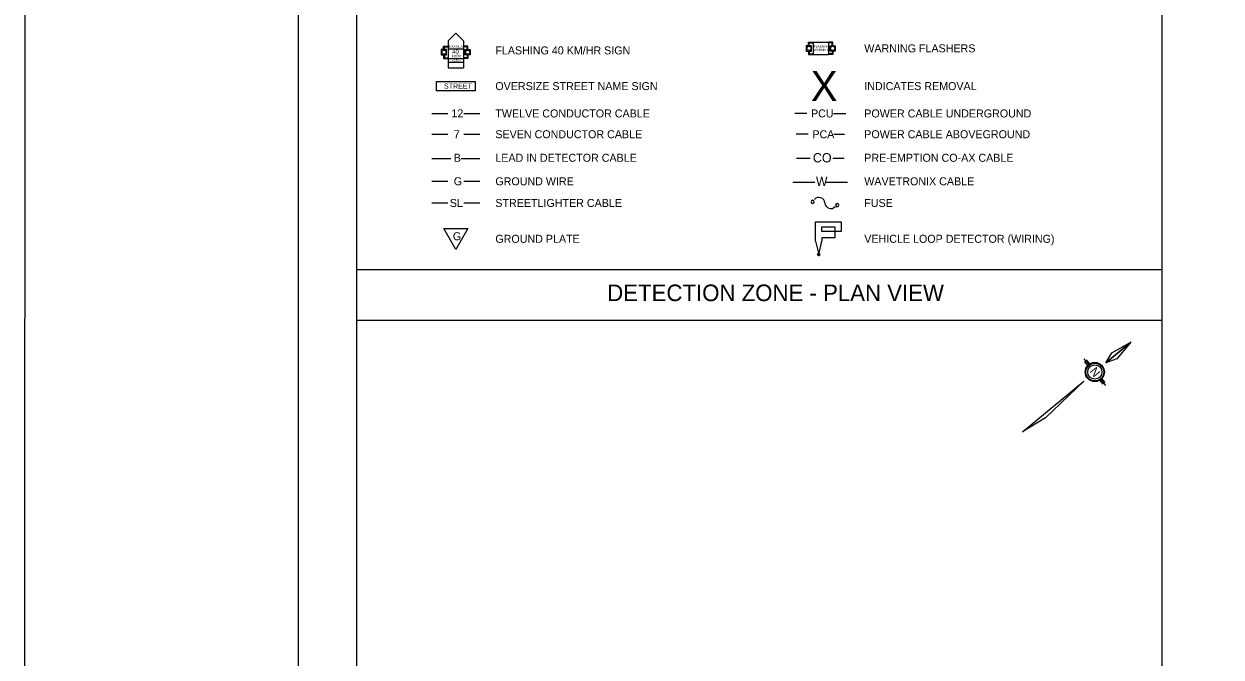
# Model space of a CAD drawing. Extents: x 595568 to 603392, y 4837996 to 4846579.
# Drawn here: x 603041.8 to 603106.7, y 4846467.9 to 4846502.2 of the extents above; entities that cross this region are included whole.
import ezdxf

# ---------------------------------------------------------------- set-up
doc = ezdxf.new("R2010")
doc.units = 0
for name, color, linetype in [('-PRINT FULLSIZE', 7, 'Continuous'), ('-PRINT HALFSIZE', 7, 'Continuous'), ('ENG_BORDER', 7, 'Continuous'), ('ENG_KEY', 7, 'Continuous'), ('ENG_TITLEBLOCK', 7, 'Continuous'), ('ENG_TX_TITLEBLOCK', 7, 'Continuous'), ('TCS_FUSE', 7, 'Continuous'), ('TCS_LEGEND', 7, 'Continuous'), ('TCS_LOOP', 7, 'Continuous'), ('TCS_PLATE', 7, 'Continuous'), ('TCS_REMOVAL', 7, 'Continuous'), ('TCS_SIGN', 7, 'Continuous'), ('TCS_WR_12', 7, 'Continuous'), ('TCS_WR_7', 7, 'Continuous'), ('TCS_WR_B', 7, 'Continuous'), ('TCS_WR_CO', 7, 'Continuous'), ('TCS_WR_G', 7, 'Continuous'), ('TCS_WR_PCA', 7, 'Continuous'), ('TCS_WR_PCU', 7, 'Continuous'), ('TCS_WR_SL', 7, 'Continuous'), ('TCS_WR_W', 7, 'Continuous')]:
    doc.layers.add(name, color=color, linetype=linetype)

msp = doc.modelspace()

# ---------------------------------------------------------------- linework, layer by layer
at = {"layer": '-PRINT FULLSIZE'}
msp.add_lwpolyline([(603041.762, 4846390.886), (603265.214, 4846390.798), (603265.274, 4846543.386), (603041.822, 4846543.475)], close=True, dxfattribs=at)
at = {"layer": '-PRINT HALFSIZE'}
msp.add_lwpolyline([(603056.659, 4846536.385), (603261.877, 4846536.304), (603261.821, 4846396.201), (603056.604, 4846396.282)], close=True, dxfattribs=at)
at = {"layer": 'ENG_BORDER'}
msp.add_line((603103.463, 4846399.391), (603103.462, 4846533.885), dxfattribs=at)
msp.add_lwpolyline([(603059.791, 4846533.885), (603059.791, 4846399.391)], dxfattribs=at)
at = {"layer": 'ENG_KEY'}
for p, q in [((603099.487, 4846483.734), (603099.222, 4846484.055)), ((603099.437, 4846483.686), (603099.259, 4846483.901)), ((603099.544, 4846483.775), (603099.366, 4846483.989)), ((603100.27, 4846482.677), (603100.092, 4846482.892)), ((603100.414, 4846482.612), (603100.148, 4846482.933)), ((603100.377, 4846482.766), (603100.199, 4846482.981))]:
    msp.add_line(p, q, dxfattribs=at)
for points in [[(603101.776, 4846484.951), (603101.006, 4846484.046), (603100.423, 4846483.833)], [(603101.776, 4846484.951), (603100.423, 4846483.833), (603100.742, 4846484.366)], [(603099.213, 4846482.833), (603097.138, 4846480.85), (603095.901, 4846480.099)]]:
    msp.add_lwpolyline(points, close=True, dxfattribs=at)
for radius in [0.52, 0.482, 0.388]:
    msp.add_circle((603099.818, 4846483.333), radius, dxfattribs=at)
at = {"layer": 'ENG_TITLEBLOCK'}
msp.add_line((603059.791, 4846486.146), (603103.462, 4846486.146), dxfattribs=at)
msp.add_lwpolyline([(603059.791, 4846488.897), (603103.462, 4846488.896)], dxfattribs=at)
at = {"layer": 'TCS_FUSE'}
for centre, radius, start, end in [((603084.521, 4846492.56), 0.0867, 0, 180), ((603084.521, 4846492.56), 0.0867, 180, 0), ((603084.867, 4846492.486), 0.319, 2.71733, 139.36608), ((603085.505, 4846492.516), 0.319, 182.71733, 319.36608), ((603085.853, 4846492.382), 0.0867, 0, 180), ((603085.853, 4846492.382), 0.0867, 180, 0)]:
    msp.add_arc(centre, radius, start, end, dxfattribs=at)
at = {"layer": 'TCS_LEGEND'}
msp.add_lwpolyline([(603099.121, 4846488.896), (603099.121, 4846488.881), (603064.132, 4846488.881), (603064.132, 4846488.897)], dxfattribs=at)
at = {"layer": 'TCS_LOOP'}
for p, q in [((603084.674, 4846491.47), (603086.062, 4846491.47)), ((603084.674, 4846490.429), (603084.674, 4846491.47)), ((603085.021, 4846491.21), (603085.715, 4846491.21)), ((603085.021, 4846490.949), (603085.021, 4846491.21)), ((603086.062, 4846490.949), (603085.021, 4846490.949)), ((603085.715, 4846491.21), (603085.715, 4846490.602)), ((603086.062, 4846491.47), (603086.062, 4846490.949)), ((603084.674, 4846490.429), (603084.847, 4846489.704)), ((603084.847, 4846489.704), (603085.021, 4846490.422)), ((603085.021, 4846490.602), (603085.021, 4846490.422)), ((603085.715, 4846490.602), (603085.021, 4846490.602)), ((603084.788, 4846489.697), (603084.854, 4846489.764)), ((603084.788, 4846489.702), (603084.849, 4846489.764)), ((603084.788, 4846489.707), (603084.844, 4846489.764)), ((603084.788, 4846489.713), (603084.839, 4846489.763)), ((603084.789, 4846489.693), (603084.859, 4846489.763)), ((603084.789, 4846489.719), (603084.832, 4846489.762)), ((603084.79, 4846489.689), (603084.863, 4846489.762)), ((603084.791, 4846489.685), (603084.867, 4846489.761)), ((603084.792, 4846489.681), (603084.87, 4846489.759)), ((603084.792, 4846489.727), (603084.824, 4846489.759)), ((603084.794, 4846489.678), (603084.874, 4846489.758)), ((603084.796, 4846489.674), (603084.877, 4846489.756)), ((603084.798, 4846489.671), (603084.88, 4846489.754)), ((603084.798, 4846489.738), (603084.813, 4846489.753)), ((603084.8, 4846489.668), (603084.883, 4846489.752)), ((603084.802, 4846489.665), (603084.886, 4846489.75)), ((603084.804, 4846489.663), (603084.889, 4846489.747)), ((603084.807, 4846489.66), (603084.891, 4846489.745)), ((603084.81, 4846489.658), (603084.894, 4846489.742)), ((603084.813, 4846489.656), (603084.896, 4846489.739)), ((603084.816, 4846489.654), (603084.898, 4846489.736)), ((603084.819, 4846489.652), (603084.9, 4846489.733)), ((603084.822, 4846489.65), (603084.901, 4846489.729)), ((603084.826, 4846489.648), (603084.903, 4846489.726)), ((603084.83, 4846489.647), (603084.904, 4846489.722)), ((603084.834, 4846489.646), (603084.905, 4846489.718)), ((603084.838, 4846489.645), (603084.906, 4846489.713)), ((603084.843, 4846489.645), (603084.907, 4846489.709)), ((603084.848, 4846489.645), (603084.907, 4846489.704)), ((603084.853, 4846489.645), (603084.907, 4846489.699)), ((603084.859, 4846489.646), (603084.906, 4846489.693)), ((603084.866, 4846489.648), (603084.904, 4846489.686)), ((603084.875, 4846489.651), (603084.9, 4846489.677))]:
    msp.add_line(p, q, dxfattribs=at)
msp.add_circle((603084.847, 4846489.704), 0.0597, dxfattribs=at)
at = {"layer": 'TCS_PLATE'}
for p, q in [((603065.176, 4846489.986), (603064.525, 4846491.113)), ((603064.525, 4846491.113), (603065.827, 4846491.113)), ((603065.827, 4846491.113), (603065.176, 4846489.986))]:
    msp.add_line(p, q, dxfattribs=at)
at = {"layer": 'TCS_SIGN'}
for p, q in [((603064.765, 4846501.294), (603065.176, 4846501.713)), ((603064.765, 4846501.294), (603064.765, 4846499.831)), ((603065.176, 4846501.713), (603065.586, 4846501.294)), ((603065.586, 4846501.294), (603065.586, 4846499.831)), ((603064.516, 4846500.814), (603064.516, 4846500.997)), ((603064.516, 4846500.997), (603064.765, 4846500.997)), ((603064.553, 4846500.961), (603064.765, 4846500.961)), ((603064.553, 4846500.814), (603064.553, 4846500.961)), ((603064.765, 4846500.866), (603065.586, 4846500.866)), ((603065.835, 4846500.997), (603065.586, 4846500.997)), ((603065.799, 4846500.961), (603065.586, 4846500.961)), ((603065.799, 4846500.814), (603065.799, 4846500.961)), ((603065.835, 4846500.814), (603065.835, 4846500.997)), ((603084.303, 4846501.029), (603084.303, 4846501.212)), ((603084.303, 4846501.212), (603084.552, 4846501.212)), ((603084.303, 4846500.739), (603084.303, 4846500.556)), ((603084.339, 4846501.176), (603084.552, 4846501.176)), ((603084.339, 4846501.029), (603084.339, 4846501.176)), ((603084.339, 4846500.739), (603084.339, 4846500.592)), ((603084.552, 4846501.212), (603084.552, 4846500.556)), ((603084.552, 4846501.212), (603085.373, 4846501.212)), ((603085.373, 4846501.212), (603085.373, 4846500.556)), ((603085.622, 4846501.212), (603085.373, 4846501.212)), ((603085.585, 4846501.176), (603085.373, 4846501.176)), ((603085.585, 4846501.029), (603085.585, 4846501.176)), ((603085.585, 4846500.739), (603085.585, 4846500.592)), ((603085.622, 4846501.029), (603085.622, 4846501.212)), ((603085.622, 4846500.739), (603085.622, 4846500.556)), ((603064.516, 4846500.525), (603064.516, 4846500.341)), ((603064.516, 4846500.341), (603064.765, 4846500.341)), ((603064.553, 4846500.525), (603064.553, 4846500.378)), ((603064.553, 4846500.378), (603064.765, 4846500.378)), ((603064.756, 4846500.336), (603065.576, 4846500.336)), ((603064.764, 4846500.134), (603065.584, 4846500.134)), ((603065.799, 4846500.378), (603065.586, 4846500.378)), ((603065.835, 4846500.341), (603065.586, 4846500.341)), ((603065.799, 4846500.525), (603065.799, 4846500.378)), ((603065.835, 4846500.525), (603065.835, 4846500.341)), ((603084.303, 4846500.556), (603084.552, 4846500.556)), ((603084.339, 4846500.592), (603084.552, 4846500.592)), ((603084.552, 4846500.556), (603085.373, 4846500.556)), ((603085.585, 4846500.592), (603085.373, 4846500.592)), ((603085.622, 4846500.556), (603085.373, 4846500.556)), ((603064.765, 4846499.831), (603065.586, 4846499.831))]:
    msp.add_line(p, q, dxfattribs=at)
for points in [[(603064.39, 4846500.525), (603064.679, 4846500.525), (603064.679, 4846500.814), (603064.39, 4846500.814)], [(603065.962, 4846500.525), (603065.673, 4846500.525), (603065.673, 4846500.814), (603065.962, 4846500.814)], [(603084.176, 4846500.739), (603084.465, 4846500.739), (603084.465, 4846501.029), (603084.176, 4846501.029)], [(603085.748, 4846500.739), (603085.459, 4846500.739), (603085.459, 4846501.029), (603085.748, 4846501.029)], [(603064.124, 4846499.093), (603066.228, 4846499.093), (603066.228, 4846498.572), (603064.124, 4846498.572)]]:
    msp.add_lwpolyline(points, close=True, dxfattribs=at)
for centre in [(603064.535, 4846500.672), (603065.817, 4846500.672), (603084.321, 4846500.884), (603085.604, 4846500.884)]:
    msp.add_circle(centre, 0.111, dxfattribs=at)
at = {"layer": 'TCS_WR_12'}
for p, q in [((603063.875, 4846497.358), (603064.742, 4846497.358)), ((603065.61, 4846497.358), (603066.477, 4846497.358))]:
    msp.add_line(p, q, dxfattribs=at)
at = {"layer": 'TCS_WR_7'}
for p, q in [((603063.875, 4846496.226), (603064.742, 4846496.226)), ((603065.61, 4846496.226), (603066.477, 4846496.226))]:
    msp.add_line(p, q, dxfattribs=at)
at = {"layer": 'TCS_WR_B'}
for p, q in [((603063.875, 4846494.906), (603064.913, 4846494.906)), ((603065.458, 4846494.906), (603066.477, 4846494.906))]:
    msp.add_line(p, q, dxfattribs=at)
at = {"layer": 'TCS_WR_CO'}
for p, q in [((603083.638, 4846494.934), (603084.393, 4846494.934)), ((603085.618, 4846494.934), (603086.229, 4846494.934))]:
    msp.add_line(p, q, dxfattribs=at)
at = {"layer": 'TCS_WR_G'}
for p, q in [((603063.875, 4846493.675), (603064.742, 4846493.675)), ((603065.61, 4846493.675), (603066.477, 4846493.675))]:
    msp.add_line(p, q, dxfattribs=at)
at = {"layer": 'TCS_WR_PCA'}
for p, q in [((603084.279, 4846496.227), (603083.623, 4846496.227)), ((603085.677, 4846496.227), (603086.243, 4846496.227))]:
    msp.add_line(p, q, dxfattribs=at)
at = {"layer": 'TCS_WR_PCU'}
for p, q in [((603084.206, 4846497.354), (603083.55, 4846497.354)), ((603085.643, 4846497.354), (603086.317, 4846497.354))]:
    msp.add_line(p, q, dxfattribs=at)
at = {"layer": 'TCS_WR_SL'}
for p, q in [((603063.875, 4846492.5), (603064.742, 4846492.5)), ((603065.61, 4846492.5), (603066.477, 4846492.5))]:
    msp.add_line(p, q, dxfattribs=at)
at = {"layer": 'TCS_WR_W'}
for p, q in [((603083.448, 4846493.631), (603084.633, 4846493.631)), ((603085.256, 4846493.631), (603086.418, 4846493.631))]:
    msp.add_line(p, q, dxfattribs=at)

# ---------------------------------------------------------------- texts
at = {"layer": 'ENG_KEY'}
msp.add_text('N', height=0.461, rotation=309.55585, dxfattribs=at).set_placement((603099.513, 4846483.358))
at = {"layer": 'ENG_TX_TITLEBLOCK'}
msp.add_text('DETECTION ZONE - PLAN VIEW', height=0.9, rotation=0.00011, dxfattribs=at).set_placement((603073.384, 4846487.178))
at = {"layer": 'TCS_LEGEND'}
for s, height, p in [('FLASHING 40 KM/HR SIGN', 0.43374, (603067.318, 4846500.555)), ('WARNING FLASHERS', 0.43374, (603087.319, 4846500.667)), ('OVERSIZE STREET NAME SIGN', 0.43374, (603067.318, 4846498.62)), ('INDICATES REMOVAL', 0.43374, (603087.319, 4846498.62)), ('TWELVE CONDUCTOR CABLE', 0.43374, (603067.318, 4846497.137)), ('POWER CABLE UNDERGROUND', 0.43374, (603087.319, 4846497.137)), ('SEVEN CONDUCTOR CABLE', 0.43374, (603067.318, 4846496.01)), ('POWER CABLE ABOVEGROUND', 0.43374, (603087.319, 4846496.01)), ('LEAD IN DETECTOR CABLE', 0.43374, (603067.318, 4846494.734)), ('PRE-EMPTION CO-AX CABLE', 0.43374, (603087.319, 4846494.734)), ('GROUND WIRE', 0.43374, (603067.318, 4846493.458)), ('WAVETRONIX CABLE', 0.43374, (603087.319, 4846493.458)), ('STREETLIGHTER CABLE', 0.43374, (603067.318, 4846492.284)), ('FUSE', 0.4337, (603087.319, 4846492.284)), ('GROUND PLATE', 0.43374, (603067.318, 4846490.34)), ('VEHICLE LOOP DETECTOR (WIRING)', 0.43374, (603087.319, 4846490.34))]:
    msp.add_text(s, height=height, dxfattribs=at).set_placement(p)
at = {"layer": 'TCS_PLATE'}
msp.add_text('G', height=0.434, dxfattribs=at).set_placement((603065.015, 4846490.478))
at = {"layer": 'TCS_REMOVAL'}
msp.add_text('X', height=1.631, dxfattribs=at).set_placement((603084.416, 4846498.021))
at = {"layer": 'TCS_SIGN'}
for s, height, p in [('MAXIMUM', 0.1265, (603064.79, 4846500.918)), ('40', 0.2318, (603064.983, 4846500.587)), ('WARNING', 0.1265, (603084.576, 4846500.731)), ('FLASHING', 0.1265, (603084.576, 4846500.921)), ('km/hr', 0.1511, (603064.954, 4846500.392)), ('FLASHING', 0.0703, (603064.965, 4846500.143)), ('WHEN ', 0.0703, (603065.041, 4846500.237))]:
    msp.add_text(s, height=height, rotation=0.00006, dxfattribs=at).set_placement(p)
msp.add_text('STREET', height=0.2773, dxfattribs=at).set_placement((603064.534, 4846498.698))
at = {"layer": 'TCS_WR_12'}
msp.add_text('12', height=0.4337, dxfattribs=at).set_placement((603064.937, 4846497.142))
at = {"layer": 'TCS_WR_7'}
msp.add_text('7', height=0.434, dxfattribs=at).set_placement((603065.065, 4846496.01))
at = {"layer": 'TCS_WR_B'}
msp.add_text('B', height=0.434, dxfattribs=at).set_placement((603065.062, 4846494.734))
at = {"layer": 'TCS_WR_CO'}
msp.add_text('CO', height=0.506, dxfattribs=at).set_placement((603084.534, 4846494.698))
at = {"layer": 'TCS_WR_G'}
msp.add_text('G', height=0.434, dxfattribs=at).set_placement((603065.065, 4846493.458))
at = {"layer": 'TCS_WR_PCA'}
msp.add_text('PCA', height=0.4303, dxfattribs=at).set_placement((603084.51, 4846496.011))
at = {"layer": 'TCS_WR_PCU'}
msp.add_text('PCU', height=0.4303, dxfattribs=at).set_placement((603084.436, 4846497.139))
at = {"layer": 'TCS_WR_SL'}
msp.add_text('SL', height=0.4337, dxfattribs=at).set_placement((603064.848, 4846492.284))
at = {"layer": 'TCS_WR_W'}
msp.add_text('W', height=0.495, dxfattribs=at).set_placement((603084.699, 4846493.427))

doc.saveas('drawing.dxf')
